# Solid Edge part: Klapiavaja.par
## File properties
Author: Türk
Template: Iso Part.par
Last saved by: Türk
Revision: 9
Application: Solid Edge
Accuracy: 0,990
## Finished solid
Body 1: solid body, 21 faces, 54 edges, 32 vertices.
  Faces by surface: cylinder 12, plane 9
  Edges by curve: line 28, circle 26
Bounding box of the edges (mm): 50.000 x 10.000 x 29.500, from (-6, -5, -23.5) to (44, 5, 6).
Cylindrical faces by radius (mm): R2 x5, R2.5 x2, R4 x2, R5 x1, R6 x1, R10 x1
Planar faces by outward normal: +x 1, +y 2, +z 1, -y 2, -z 1, oblique 2
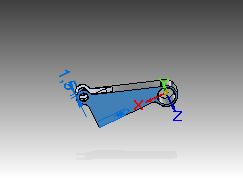
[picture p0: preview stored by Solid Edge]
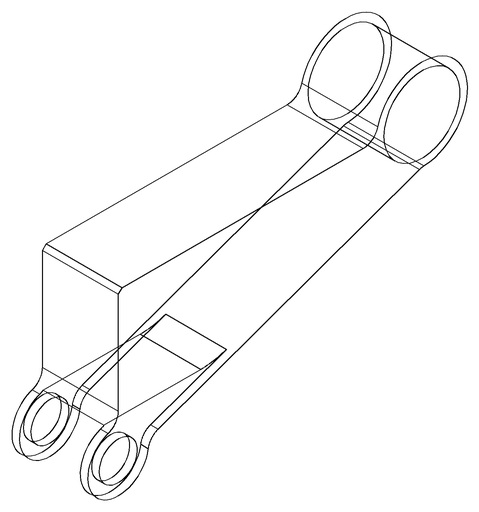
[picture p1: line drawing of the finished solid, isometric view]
